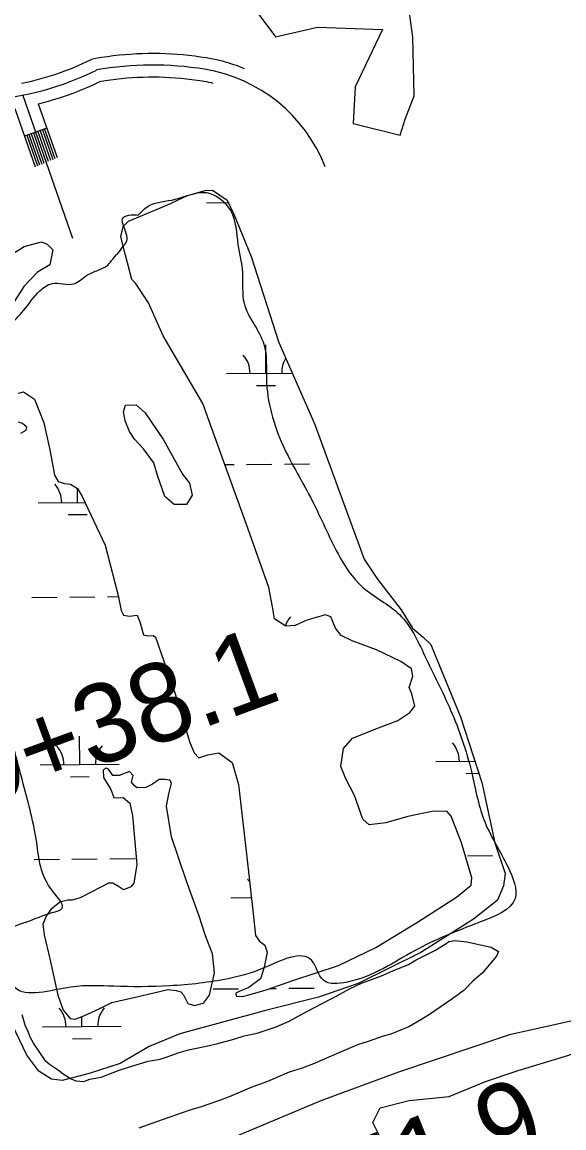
# Model space of a CAD drawing. Extents: x 3568792 to 3606828, y 529143 to 554785.
# Drawn here: x 3574736 to 3575423, y 537886 to 539290 of the extents above; entities that cross this region are included whole.
import ezdxf

# ---------------------------------------------------------------- set-up
doc = ezdxf.new("R2010")
doc.units = 0
for name, color, linetype in [('V-BORW-LINE', 7, 'Continuous'), ('V-ROAD-CNTR', 7, 'Continuous'), ('V-SITE-VEGE', 7, 'Continuous'), ('V-SURV-IDEN', 7, 'Continuous'), ('V-WETL-SWMP', 7, 'Continuous')]:
    doc.layers.add(name, color=color, linetype=linetype)

msp = doc.modelspace()

# ---------------------------------------------------------------- linework, layer by layer
at = {"layer": 'V-BORW-LINE'}
for points in [[(3575221.6, 539166.4), (3575233.2, 539196.2), (3575231.7, 539270.7), (3575221.2, 539345.4), (3575242.3, 539395.7), (3575275.2, 539444), (3575268.4, 539488.8), (3575199, 539539.9), (3575122, 539577.1), (3575030.3, 539587.8), (3574971.4, 539563.7), (3574951, 539523.2), (3574945.2, 539441.5), (3574986.1, 539368.6), (3575014.4, 539328.5), (3575057.2, 539271.1), (3575110.4, 539283.3), (3575192.9, 539280.4), (3575158.4, 539207.3), (3575155.9, 539160.8), (3575215.4, 539146), (3575221.6, 539166.4)], [(3575751.2, 537862.5), (3575746.1, 537893.3), (3575731.7, 537922.9), (3575707.2, 537960.6), (3575665.2, 538005.4), (3575626.1, 538047), (3575570.5, 538058.6), (3575498.4, 538036.1), (3575354, 538004), (3575213.2, 537956.5), (3575114.8, 537920.5), (3575006.8, 537874.9)], [(3575190.2, 537874.4), (3575180.8, 537892.8), (3575189.9, 537911.4), (3575226.8, 537920.9), (3575277.6, 537926), (3575323.6, 537944.8), (3575365.1, 537959), (3575429.7, 537978.1), (3575503.3, 538011), (3575549.3, 538034.5), (3575590.8, 538053.4), (3575637.2, 538021.4), (3575669.8, 537994), (3575693.2, 537961.8), (3575707.3, 537929.6), (3575716.7, 537911.2), (3575712.3, 537892.7), (3575670.7, 537883.1)]]:
    msp.add_lwpolyline(points, dxfattribs=at)
msp.add_spline([(3574882.8, 539044.7), (3574874, 539044.8), (3574863.8, 539041.2), (3574866.1, 539026.8), (3574866.6, 539008), (3574865.2, 539006.6), (3574858.9, 538998), (3574855.2, 538994.1), (3574843, 538980.2), (3574832.3, 538974.7), (3574818, 538968.3), (3574801.4, 538957.5), (3574773.7, 538957.7), (3574758, 538948.3), (3574737.6, 538923.4), (3574718.5, 538904.1), (3574688.1, 538881.3), (3574659.1, 538862.6), (3574648.7, 538832.8), (3574643.1, 538780.2), (3574644.7, 538738.9), (3574655.4, 538673.1), (3574667.8, 538612.5), (3574683.6, 538548.3), (3574695.9, 538495.6), (3574714.1, 538412.2), (3574737.2, 538322.8), (3574754.2, 538248.2), (3574775.1, 538185.5), (3574786.5, 538164.7), (3574773.5, 538159.2), (3574742.9, 538148.1), (3574732.2, 538144.5), (3574712.8, 538131.8), (3574713.8, 538098.1), (3574726.4, 538064.2), (3574797.7, 538064.7), (3574852, 538065.7), (3574922.8, 538066.3), (3574997.1, 538075.3), (3575040.3, 538088.2), (3575103.4, 538098.4), (3575118.1, 538073.5), (3575148.2, 538071), (3575233.8, 538110.9), (3575317.2, 538147.4), (3575361.4, 538177.2), (3575352.4, 538216.8), (3575321.6, 538277.4), (3575305.9, 538338.3), (3575279.4, 538416.4), (3575246.5, 538485.8), (3575214.7, 538537.5), (3575167.8, 538572.3), (3575136.6, 538614.6), (3575103.8, 538682.1), (3575066.7, 538752.4), (3575045.7, 538836.6), (3575042.6, 538880.6), (3575017.3, 538932.9), (3575015.3, 538971.3), (3575009.6, 539007.2), (3575000, 539050.6), (3574969.8, 539073.2), (3574929.9, 539064.7), (3574897.1, 539056.7), (3574882.8, 539044.7)], degree=3, dxfattribs=at)
at = {"layer": 'V-ROAD-CNTR'}
msp.add_line((3574767.1, 539154.8), (3574738.8, 539144.9), dxfattribs=at)
for points in [[(3574734.8, 539212), (3574743.6, 539213.9), (3574749.5, 539215.2), (3574755.4, 539216.7), (3574761.2, 539218.3), (3574767.1, 539220), (3574772.9, 539221.7), (3574778.6, 539223.6), (3574784.3, 539225.6), (3574790, 539227.7), (3574795.7, 539229.9), (3574801.3, 539232.1), (3574806.9, 539234.5), (3574812.5, 539237), (3574817.9, 539239.5), (3574825.4, 539243.2), (3574829.3, 539243.9), (3574836.6, 539245.1), (3574843.9, 539246.1), (3574851.3, 539247.1), (3574858.7, 539247.9), (3574866, 539248.6), (3574873.4, 539249.1), (3574880.8, 539249.6), (3574888.2, 539249.8), (3574895.6, 539250), (3574903, 539250), (3574910.4, 539250), (3574917.8, 539249.7), (3574925.3, 539249.3), (3574932.6, 539248.9), (3574940, 539248.3), (3574947.4, 539247.5), (3574954.7, 539246.7), (3574962.1, 539245.7), (3574969.4, 539244.5), (3574971.4, 539244.2), (3574975.1, 539243.6), (3574978.7, 539242.8), (3574982.3, 539242), (3574986, 539241.2), (3574989.6, 539240.3), (3574993.2, 539239.3), (3574996.8, 539238.3), (3575000.3, 539237.2), (3575003.9, 539236), (3575007.4, 539234.8), (3575010.9, 539233.5), (3575014.3, 539232.2), (3575017.4, 539230.9)], [(3574756.2, 539186), (3574763, 539187.7), (3574769.3, 539189.4), (3574775.6, 539191.2), (3574781.9, 539193.1), (3574788.2, 539195.2), (3574794.4, 539197.3), (3574800.6, 539199.6), (3574806.7, 539201.9), (3574812.9, 539204.4), (3574818.9, 539207), (3574824.9, 539209.7), (3574830.9, 539212.5), (3574834.8, 539214.4), (3574834.3, 539214.3), (3574841.2, 539215.4), (3574848, 539216.4), (3574854.8, 539217.3), (3574861.6, 539218), (3574868.5, 539218.7), (3574875.4, 539219.2), (3574882.2, 539219.6), (3574889.1, 539219.8), (3574896, 539220), (3574902.9, 539220), (3574909.8, 539220), (3574916.6, 539219.8), (3574923.5, 539219.4), (3574930.4, 539219), (3574937.2, 539218.4), (3574944.1, 539217.7), (3574951, 539216.9), (3574957.8, 539216), (3574964.6, 539214.9), (3574966.3, 539214.6), (3574969.5, 539214.1), (3574972.6, 539213.5), (3574975.8, 539212.8), (3574977.6, 539212.3)], [(3574799.9, 539015.1), (3574736.5, 539197.1)], [(3574726.5, 539180.1), (3574752.3, 539106)], [(3574756.2, 539186), (3574780, 539117.7)], [(3574750.1, 539148.9), (3574763.4, 539110.7)], [(3574752.9, 539149.8), (3574766.1, 539111.9)], [(3574755.7, 539150.8), (3574768.9, 539113)], [(3574758.6, 539151.8), (3574771.7, 539114.2)], [(3574761.4, 539152.8), (3574774.5, 539115.4)], [(3574764.2, 539153.8), (3574777.2, 539116.6)], [(3574741.6, 539145.9), (3574755.1, 539107.2)], [(3574744.4, 539146.9), (3574757.8, 539108.4)], [(3574747.3, 539147.9), (3574760.6, 539109.5)]]:
    msp.add_lwpolyline(points, dxfattribs=at)
for centre, radius, start, end in [((3574901.3, 538825.6), 409.5, 80.7668, 100.0101), ((3574668, 539553.1), 362.6, 273.5597, 296.5634), ((3574935.5, 539033.8), 198.5, 21.3216, 80.8734)]:
    msp.add_arc(centre, radius, start, end, dxfattribs=at)
at = {"layer": 'V-SITE-VEGE'}
for points in [[(3575151.9, 538063), (3575166.3, 538069.7), (3575191.9, 538079.2), (3575206.3, 538085.2), (3575226, 538093.3), (3575235.8, 538099.3), (3575259.3, 538111.3), (3575272.4, 538119.3), (3575277, 538122.6), (3575284.9, 538124), (3575300, 538122.2), (3575331, 538115.2), (3575340.2, 538110), (3575337.7, 538104.1), (3575320.1, 538082.9), (3575307.7, 538072.3), (3575296.6, 538061), (3575282.2, 538050.3), (3575252.8, 538029.7), (3575241.7, 538023), (3575226.6, 538014.3), (3575218.1, 538011), (3575203.7, 538004.9), (3575193.9, 538002.2), (3575174.9, 537995.5), (3575161.1, 537991.4), (3575137.5, 537981.3), (3575105.4, 537967.3), (3575091, 537961.9), (3575074.6, 537956.5), (3575047, 537945), (3575027.4, 537937.6), (3575000.5, 537926.2), (3574984.8, 537920.2), (3574963.1, 537912.7), (3574947.4, 537908), (3574906.1, 537893.8), (3574883.8, 537885.7)], [(3574735.2, 538029.8), (3574737.3, 538022.6), (3574739.3, 538016.7), (3574743.3, 538007.5), (3574746, 538000.9), (3574751.4, 537991.1), (3574764, 537972.2), (3574770.6, 537967), (3574781.9, 537959.2), (3574787.9, 537954.6), (3574797.8, 537948.1), (3574803.7, 537945.6), (3574814.2, 537945), (3574821.5, 537947.7), (3574835.9, 537950.4), (3574858.8, 537959.2), (3574870.6, 537963.2), (3574895.6, 537970.7), (3574910.7, 537973.4), (3574919.8, 537976.2), (3574934.9, 537981.6), (3574946.7, 537984.9), (3574969.1, 537989.7), (3574984.1, 537993.2), (3575004.5, 537998.6), (3575017.6, 538002.7), (3575034, 538006.1), (3575058.3, 538014.2), (3575074.7, 538021.6), (3575091.7, 538030.9), (3575114.6, 538043), (3575130.3, 538051), (3575151.9, 538063)]]:
    msp.add_lwpolyline(points, dxfattribs=at)
at = {"layer": 'V-WETL-SWMP'}
for p, q in [((3574969.8, 539060.4), (3574997.5, 539060.6)), ((3575045.1, 538843.8), (3575044.8, 538879.8)), ((3574995.1, 538843.4), (3575078.5, 538844.1)), ((3575033.2, 538828.3), (3575057.2, 538828.5)), ((3574993, 538727.9), (3575004.6, 538728)), ((3575020.6, 538728.2), (3575052.6, 538728.4)), ((3575068.6, 538728.6), (3575100.6, 538728.8)), ((3574806, 538679.9), (3574805.8, 538697.8)), ((3574756, 538679.5), (3574815.3, 538680)), ((3574794.1, 538664.4), (3574818.1, 538664.6)), ((3574748.2, 538559.3), (3574780.2, 538559.6)), ((3574796.1, 538559.7), (3574828.1, 538560)), ((3574844.1, 538560.2), (3574857.8, 538560.3)), ((3574808.8, 538347.2), (3574808.5, 538383.2)), ((3575260.7, 538351.1), (3575310.3, 538351.5)), ((3574758.8, 538346.8), (3574858.8, 538347.7)), ((3575298.8, 538335.9), (3575315.2, 538336.1)), ((3574796.9, 538331.7), (3574820.9, 538331.9)), ((3574751, 538226.7), (3574783, 538227)), ((3574799, 538227.1), (3574831, 538227.4)), ((3574847, 538227.5), (3574879, 538227.8)), ((3575300.8, 538231.3), (3575332.8, 538231.6)), ((3575000.7, 538178), (3575026.6, 538178.3)), ((3574978.3, 538062.4), (3575010.3, 538062.7)), ((3575050.2, 538063), (3575058.3, 538063.1)), ((3575074.3, 538063.2), (3575106.3, 538063.5)), ((3574811.6, 538014.6), (3574811.5, 538027.2)), ((3574761.6, 538014.2), (3574861.6, 538015)), ((3574799.7, 537999.1), (3574823.7, 537999.3))]:
    msp.add_line(p, q, dxfattribs=at)
for points in [[(3574789.3, 538703.8), (3574797.1, 538702.9), (3574806, 538697.7), (3574811.8, 538687.4), (3574840.9, 538625.8), (3574857.6, 538561.6), (3574861.4, 538542.9), (3574864.5, 538536.7), (3574871.8, 538535.7), (3574881.7, 538536.8), (3574884.9, 538528.5), (3574889.7, 538512), (3574895.4, 538510.4), (3574902.2, 538511), (3574904.8, 538509), (3574929.8, 538437), (3574948.5, 538375.3), (3574953.9, 538361.9), (3574960.1, 538355.7), (3574971.5, 538359.4), (3574985.5, 538362.1), (3575002.3, 538349.8), (3575010.3, 538321.8), (3575020.4, 538233.6), (3575028.9, 538158.3), (3575031.7, 538130.3), (3575037, 538123.1), (3575043.8, 538117.9), (3575046.5, 538109.1), (3575043, 538089.9), (3575038.4, 538075.3), (3575023.5, 538064.2), (3575011.1, 538058.9), (3575006.9, 538056.8), (3575007.5, 538053.2), (3575015.3, 538052.7), (3575025.1, 538055.4), (3575045.3, 538061.3), (3575080.5, 538073.6), (3575137, 538092.3), (3575184.6, 538115), (3575237.3, 538147.2), (3575286.9, 538178.8), (3575305.5, 538194), (3575306.4, 538203.4), (3575293.1, 538247.9), (3575280.3, 538281.6), (3575275.1, 538287.8), (3575257.9, 538288.1), (3575225.2, 538281.1), (3575197.3, 538273.1), (3575176, 538270.8), (3575168.1, 538278), (3575157.5, 538308), (3575146.4, 538329.2), (3575140, 538344.8), (3575143.4, 538367.7), (3575154.8, 538380.8), (3575187.9, 538394), (3575212.7, 538403.1), (3575227.7, 538413.1), (3575233.9, 538421.4), (3575230.1, 538437), (3575226.9, 538444.8), (3575231.5, 538459.3), (3575229.8, 538468.7), (3575216.2, 538477.9), (3575185.5, 538492.7), (3575154.7, 538504.4), (3575140.6, 538511), (3575133.3, 538520.3), (3575127.4, 538534.8), (3575120.7, 538537.4), (3575096.8, 538530.4), (3575082.3, 538523.5), (3575070.4, 538522.9), (3575055.8, 538532.1), (3575053.5, 538547.2), (3575048.7, 538572.1), (3575022, 538647.2), (3574991.7, 538731.6), (3574965.1, 538805.6), (3574914.9, 538891.4), (3574895.9, 538933.4), (3574879.6, 538958.1), (3574874.8, 538962.8), (3574866.8, 538993.9), (3574860.9, 539017.2), (3574863.9, 539030.2), (3574870.6, 539037), (3574919.2, 539057.2), (3574945.6, 539069.4), (3574967.9, 539075.8), (3574977.2, 539076.4), (3574996.1, 539063.6), (3575004.5, 539046), (3575026.3, 538992.2), (3575061.5, 538882.8), (3575107.1, 538778.8), (3575142.2, 538683), (3575169.9, 538607.9)], [(3574722.3, 538994.7), (3574738.4, 539004.7), (3574760.1, 539010.6), (3574767.4, 539007.6), (3574774.8, 539000.4), (3574770.8, 538981.6), (3574755.3, 538972.1), (3574737.8, 538953.8), (3574722.9, 538930.8)], [(3574731.1, 538818.7), (3574737.4, 538820.3), (3574751.5, 538811), (3574763.2, 538781), (3574770.7, 538746.8), (3574776.7, 538714.6), (3574781.5, 538706.4), (3574789.3, 538703.8)], [(3574734.2, 538767.8), (3574740.9, 538771.5), (3574741.9, 538775.6), (3574736.2, 538780.3), (3574731, 538781.8)], [(3575169.9, 538607.9), (3575186.8, 538582.6), (3575216.7, 538543.4), (3575230.9, 538520.1), (3575244.6, 538508.8), (3575254.5, 538499.6), (3575258.7, 538489.2), (3575292.2, 538407.9), (3575318.9, 538324.5), (3575335.7, 538247.8), (3575348.5, 538208.9), (3575346.5, 538193.3), (3575338.9, 538175.1), (3575308.5, 538150.9), (3575241.8, 538108.8), (3575162.1, 538069.1), (3575111.9, 538052), (3575046.1, 538035.4), (3574935.7, 538005.3), (3574896.8, 537989.4), (3574860.1, 537967.8), (3574820.8, 537954.9), (3574786.6, 537946.3), (3574773, 537947.8), (3574756.8, 537958), (3574741.6, 537978.1), (3574723.6, 538016.4)]]:
    msp.add_lwpolyline(points, dxfattribs=at)
for points in [[(3574871.8, 538770), (3574866.5, 538783.5), (3574864.4, 538794.9), (3574866.9, 538803.2), (3574880.4, 538803.9), (3574891.9, 538793.6), (3574915.1, 538759.5), (3574939.3, 538716), (3574948.3, 538704.2), (3574951.5, 538689.1), (3574944.4, 538677.1), (3574928.8, 538677.5), (3574916.7, 538687.3), (3574907.7, 538714.2), (3574902.8, 538730.3), (3574889.7, 538747.8), (3574878.2, 538760.2)], [(3574799.1, 538175), (3574793.9, 538175), (3574783.5, 538172.3), (3574772.2, 538163.4), (3574766.5, 538155.5), (3574762, 538144.6), (3574763.6, 538131.1), (3574770.7, 538100.5), (3574780.9, 538054.3), (3574787.9, 538035.2), (3574796.8, 538024.9), (3574803, 538023.9), (3574813.9, 538028.1), (3574833.6, 538037.1), (3574849.6, 538045.1), (3574886.9, 538053.7), (3574920.6, 538061.8), (3574931, 538060.3), (3574937.3, 538058.8), (3574940.4, 538054.7), (3574946.2, 538043.8), (3574954.6, 538041.3), (3574966, 538044.5), (3574973.7, 538054.5), (3574979.7, 538082.6), (3574977.4, 538107), (3574968.4, 538129.7), (3574960.3, 538154.6), (3574944.4, 538199.2), (3574925.2, 538255.6), (3574919.1, 538294.5), (3574922.1, 538310.1), (3574925.1, 538323.7), (3574923, 538327.3), (3574917.3, 538328.3), (3574909.5, 538328.2), (3574901.2, 538322.4), (3574892.9, 538318.2), (3574881.5, 538317.6), (3574878.4, 538320.2), (3574874.7, 538324.8), (3574876.7, 538333.1), (3574872, 538338.3), (3574859, 538333.5), (3574850.7, 538333.4), (3574845.5, 538341.2), (3574842.3, 538342.7), (3574838.7, 538340.1), (3574838.8, 538330.7), (3574848.3, 538315.7), (3574852, 538305.4), (3574855.1, 538304.9), (3574864, 538305.5), (3574872.3, 538298.3), (3574875.6, 538282.2), (3574878.4, 538253.7), (3574881.3, 538220.4), (3574877.4, 538196.5), (3574873.8, 538191.8), (3574864.5, 538188.1), (3574858.2, 538192.2), (3574850.9, 538196.8), (3574845.2, 538196.7), (3574836.4, 538192), (3574809.5, 538178.2)]]:
    msp.add_lwpolyline(points, close=True, dxfattribs=at)
for centre, start, end in [((3574989.8, 538843.8), 359.7115, 41.2552), ((3575100.3, 538844.7), 148.6869, 181.2552), ((3574750.7, 538679.9), 359.7115, 41.2552), ((3575103.1, 538512.1), 139.7115, 161.409), ((3574753.5, 538347.3), 359.7115, 41.2552), ((3574864, 538348.2), 139.7115, 181.2552), ((3575255.4, 538351.5), 359.7115, 41.2552), ((3574995.4, 538178.5), 34.8744, 41.2552), ((3574756.3, 538014.6), 359.7115, 41.2552), ((3574866.8, 538015.5), 139.7115, 181.2552)]:
    msp.add_arc(centre, 35.2, start, end, dxfattribs=at)

# ---------------------------------------------------------------- texts
at = {"layer": 'V-SURV-IDEN'}
for s, rotation, p in [('2709+38.1', 20.1275, (3574470.5, 538211.9)), ('2715+51.9', 21.795, (3574815.3, 537625.1))]:
    msp.add_text(s, height=100, rotation=rotation, dxfattribs=at).set_placement(p)

doc.saveas('drawing.dxf')
